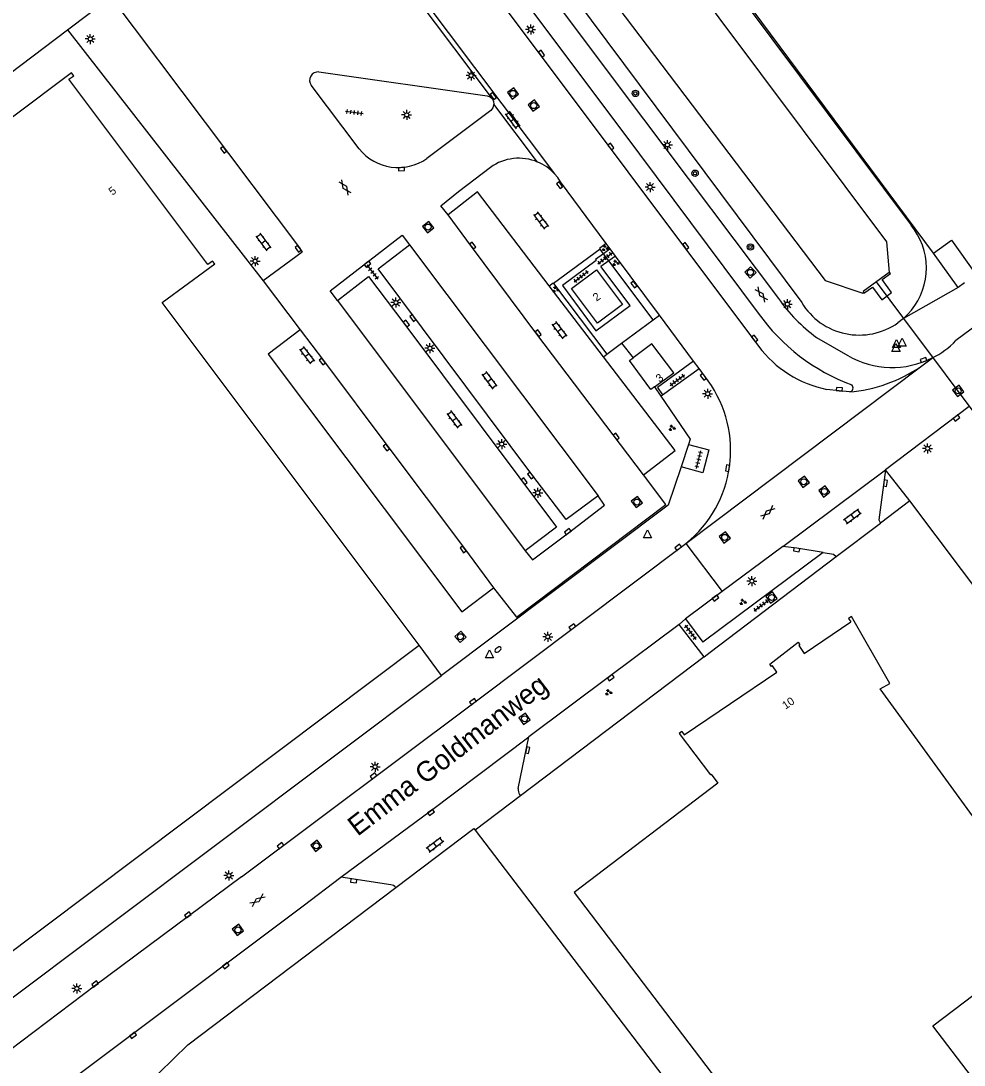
# Model space of a CAD drawing. Extents: x 126000 to 131009, y 393000 to 395500.
# Drawn here: x 130725.6 to 130843.4, y 394178.9 to 394309.3 of the extents above; entities that cross this region are included whole.
import ezdxf

# ---------------------------------------------------------------- set-up
doc = ezdxf.new("R2010")
doc.units = 0
for name, color, linetype in [('gg-afsc-hekwerk', 7, 'Continuous'), ('gg-anno-huisnummerreeks BGT', 7, 'Continuous'), ('gg-anno-openbare ruimte label', 7, 'Continuous'), ('gg-bbg-bijgebouw', 7, 'Continuous'), ('gg-bbg-hoofdgebouw', 7, 'Continuous'), ('gg-knt-verharding', 7, 'Continuous'), ('gg-knt-verharding nz', 7, 'Continuous'), ('gg-kntw-bovenkant insteek waterloop', 7, 'Continuous'), ('gg-kwrk-duiker nz buis', 7, 'Continuous'), ('gg-kwrk-uitstroombak niveau min 01', 7, 'Continuous'), ('gt-grn-groengrens', 7, 'Continuous'), ('gt-grn-weggrens', 7, 'Continuous'), ('gt-symb-boom', 7, 'Continuous'), ('gt-symb-brandkraan', 7, 'Continuous'), ('gt-symb-gesloten verharding', 7, 'Continuous'), ('gt-symb-groenvak', 7, 'Continuous'), ('gt-symb-klinker verharding', 7, 'Continuous'), ('gt-symb-kolk', 7, 'Continuous'), ('gt-symb-lichtmast', 7, 'Continuous'), ('gt-symb-rioolschacht', 7, 'Continuous'), ('gt-symb-tegel verharding', 7, 'Continuous'), ('gt-symb-waterafsluiter', 7, 'Continuous'), ('gx-grn-maaiveld', 7, 'Continuous')]:
    doc.layers.add(name, color=color, linetype=linetype)

# ---------------------------------------------------------------- blocks, each defined once
blk = doc.blocks.new('gt0-BOOM')
at = {"layer": 'gt-symb-boom'}
for radius in [0.4, 0.2]:
    blk.add_circle((0, 0), radius, dxfattribs=at)
blk = doc.blocks.new('gt0-LMAST')
at = {"layer": 'gt-symb-lichtmast'}
for p, q in [((-0.18, 0.17), (-0.45, 0.44)), ((0, 0.25), (0, 0.62)), ((0.17, 0.17), (0.44, 0.44)), ((-0.25, 0), (-0.63, 0)), ((-0.18, -0.18), (-0.45, -0.45)), ((0, -0.25), (0, -0.63)), ((0.44, -0.45), (0.17, -0.18)), ((0.25, 0), (0.62, 0))]:
    blk.add_line(p, q, dxfattribs=at)
blk.add_circle((0, 0), 0.25, dxfattribs=at)
blk = doc.blocks.new('gt0-GRVAK')
at = {"layer": 'gt-symb-groenvak'}
for p, q in [((-0.11, 0.19), (-0.23, 0.24)), ((-0.18, 0.15), (0.09, 0.15)), ((-0.09, 0.21), (-0.16, 0.32)), ((-0.05, 0.21), (-0.05, 0.39)), ((0, 0.21), (0.06, 0.32)), ((0.01, 0.19), (0.13, 0.24)), ((0.26, -0.05), (0.2, 0.06)), ((0.3, -0.05), (0.3, 0.13)), ((0.35, -0.05), (0.41, 0.06)), ((-0.25, -0.23), (-0.36, -0.18)), ((-0.32, -0.26), (-0.05, -0.26)), ((-0.23, -0.21), (-0.29, -0.1)), ((-0.18, -0.2), (-0.18, -0.02)), ((-0.14, -0.21), (-0.07, -0.1)), ((-0.12, -0.23), (0, -0.18)), ((0.24, -0.07), (0.12, -0.02)), ((0.17, -0.11), (0.44, -0.11)), ((0.37, -0.07), (0.49, -0.02))]:
    blk.add_line(p, q, dxfattribs=at)
blk = doc.blocks.new('gt0-KOLK')
at = {"layer": 'gt-symb-kolk'}
blk.add_lwpolyline([(0, 0), (0.38, 0), (0.38, 0.4), (-0.37, 0.4), (-0.37, 0), (0, 0)], dxfattribs=at)
blk = doc.blocks.new('gt0-TEG1')
at = {"layer": 'gt-symb-tegel verharding'}
for p, q in [((-1.12, 0), (1.12, 0)), ((-0.9, -0.25), (-0.9, 0.25)), ((-0.45, -0.25), (-0.45, 0.25)), ((0, -0.25), (0, 0.25)), ((0.45, -0.25), (0.45, 0.25)), ((0.9, -0.25), (0.9, 0.25))]:
    blk.add_line(p, q, dxfattribs=at)
blk = doc.blocks.new('gt0-RS')
at = {"layer": 'gt-symb-rioolschacht'}
blk.add_lwpolyline([(-0.5, -0.5), (0.5, -0.5), (0.5, 0.5), (-0.5, 0.5)], close=True, dxfattribs=at)
blk.add_circle((0, 0), 0.375, dxfattribs=at)
blk = doc.blocks.new('gt0-KL1')
at = {"layer": 'gt-symb-klinker verharding'}
for p, q in [((-1.15, 0.3), (1.15, 0.3)), ((-1, -0.3), (-1, 0.3)), ((-0.5, 0.3), (-0.5, 0.45)), ((0, -0.3), (0, 0.3)), ((0.5, 0.3), (0.5, 0.45)), ((1, -0.3), (1, 0.3)), ((-1.15, -0.3), (1.15, -0.3)), ((-0.5, -0.45), (-0.5, -0.3)), ((0.5, -0.45), (0.5, -0.3))]:
    blk.add_line(p, q, dxfattribs=at)
blk = doc.blocks.new('gt0-WAFSL')
at = {"layer": 'gt-symb-waterafsluiter'}
for p, q in [((-0.5, -0.33), (0, 0.67)), ((0, 0.67), (0.5, -0.33)), ((0.5, -0.33), (-0.5, -0.33))]:
    blk.add_line(p, q, dxfattribs=at)
blk = doc.blocks.new('gt0-GESVH1')
at = {"layer": 'gt-symb-gesloten verharding'}
for p, q in [((-0.99, -0.26), (0.01, 0.24)), ((0.01, -0.26), (-0.99, 0.24)), ((0.01, 0.24), (1.01, -0.26)), ((1.01, 0.24), (0.01, -0.26))]:
    blk.add_line(p, q, dxfattribs=at)
blk = doc.blocks.new('gt0-BR')
at = {"layer": 'gt-symb-brandkraan'}
for centre, radius, start, end in [((-0.24, 0), 0.206, 107.5669, 252.4331), ((0.6, -2.66), 3, 106.892, 107.5669), ((0, -0.69), 0.938, 73.108, 106.892), ((-0.6, -2.66), 3, 72.4331, 73.108), ((0.24, 0), 0.206, 287.567, 72.4331), ((0.6, 2.66), 3, 252.4331, 253.108), ((0, 0.69), 0.938, 253.108, 286.8921), ((-0.6, 2.66), 3, 286.8921, 287.567)]:
    blk.add_arc(centre, radius, start, end, dxfattribs=at)

msp = doc.modelspace()

# ---------------------------------------------------------------- linework, layer by layer
at = {"layer": 'gg-afsc-hekwerk'}
for p, q in [((130839.62, 394280.32), (130730.73, 394427.13)), ((130839.62, 394280.32), (130772.2, 394371.21)), ((130797.97, 394280.85), (130792.18, 394276.56)), ((130798.41, 394280.26), (130797.97, 394280.85)), ((130799.09, 394279.37), (130798.41, 394280.26)), ((130804.6, 394272.01), (130799.09, 394279.37)), ((130792.18, 394276.56), (130798.82, 394267.74)), ((130800.66, 394269.1), (130804.6, 394272.01)), ((130798.82, 394267.74), (130800.66, 394269.1)), ((130800.66, 394269.1), (130802.09, 394267.28)), ((130804.78, 394263.66), (130805.58, 394262.49)), ((130809.03, 394256.44), (130808.1, 394253.66)), ((130836.65, 394249.39), (130833.02, 394246.64)), ((130896.14, 394170.36), (130836.65, 394249.39)), ((130827.47, 394242.44), (130833.02, 394246.64)), ((130811.71, 394230.51), (130827.47, 394242.44)), ((130778.17, 394227.61), (130775.4, 394231.4)), ((130810.96, 394229.93), (130811.71, 394230.51)), ((130810.96, 394229.93), (130788.05, 394212.57)), ((130674.43, 394149.73), (130778.17, 394227.61)), ((130788.05, 394212.57), (130782.38, 394208.28)), ((130782.38, 394208.28), (130824.29, 394153.36))]:
    msp.add_line(p, q, dxfattribs=at)
for points in [[(130805.58, 394262.49), (130809.25, 394257.09), (130809.03, 394256.44)], [(130808.1, 394253.66), (130806.48, 394248.85), (130778.17, 394227.61)], [(130772.45, 394201.12), (130782.21, 394208.5), (130782.38, 394208.28)], [(130725.71, 394163.65), (130727.62, 394165.25), (130737.58, 394172.73), (130739.41, 394174.39), (130742.89, 394177.98), (130746.47, 394181.48), (130772.45, 394201.12)]]:
    msp.add_lwpolyline(points, dxfattribs=at)
at = {"layer": 'gg-bbg-bijgebouw'}
for p, q in [((130842.69, 394276.05), (130839.62, 394280.32)), ((130843.49, 394276.63), (130842.69, 394276.05))]:
    msp.add_line(p, q, dxfattribs=at)
msp.add_lwpolyline([(130839.62, 394280.32), (130841.86, 394281.96), (130844.89, 394277.75)], dxfattribs=at)
at = {"layer": 'gg-bbg-hoofdgebouw'}
msp.add_line((130671.64, 394153.43), (130775.4, 394231.4), dxfattribs=at)
for points in [[(130775.4, 394231.4), (130743.26, 394274.17), (130749.85, 394278.99), (130749.57, 394279.36), (130748.97, 394278.92), (130731.63, 394302.05), (130732.23, 394302.5), (130731.96, 394302.86), (130724.59, 394297.33), (130721.82, 394300.97)], [(130794.42, 394275.93), (130797.55, 394278.27), (130800.77, 394273.94), (130797.67, 394271.61), (130794.42, 394275.93)], [(130804.78, 394263.66), (130807.17, 394265.39), (130804.44, 394269.03), (130802.09, 394267.28)], [(130804.78, 394263.66), (130804.32, 394263.33), (130801.64, 394266.95), (130802.09, 394267.28)], [(130808.18, 394220.62), (130808.5, 394220.18), (130820.05, 394228.02), (130819.51, 394228.81), (130819.38, 394228.73), (130819.17, 394229.03), (130822.72, 394231.76), (130822.94, 394231.43), (130822.82, 394231.35), (130823.49, 394230.35), (130829.28, 394234.29)], [(130848.64, 394171.9), (130839.55, 394183.84), (130855.04, 394195.59), (130832.97, 394225.91), (130834.19, 394226.6), (130829.38, 394234.95), (130829.02, 394234.73), (130829.28, 394234.29)], [(130808.18, 394220.62), (130807.84, 394220.37), (130811.77, 394215.21), (130811.85, 394215.26), (130812.68, 394214.15), (130794.75, 394200.51), (130828.31, 394156.42)]]:
    msp.add_lwpolyline(points, dxfattribs=at)
at = {"layer": 'gg-knt-verharding'}
for p, q in [((130732.16, 394370.3), (130792.27, 394290.26)), ((130755.2, 394352.22), (130817.77, 394268.72)), ((130784.52, 394299.61), (130748.05, 394348.26)), ((130721.82, 394300.97), (130731.44, 394308.25)), ((130731.44, 394308.25), (130755.89, 394276.89)), ((130767.89, 394293.35), (130761.89, 394301.31)), ((130790.18, 394291.72), (130784.72, 394298.93)), ((130774.17, 394281.4), (130797.73, 394250.02)), ((130799.25, 394280.87), (130798.74, 394281.56)), ((130799.25, 394280.87), (130798.41, 394280.26)), ((130799.92, 394279.96), (130799.09, 394279.37)), ((130799.92, 394279.96), (130799.25, 394280.87)), ((130805.4, 394272.58), (130799.92, 394279.96)), ((130799.09, 394279.37), (130798.09, 394278.66)), ((130755.89, 394276.89), (130760.5, 394270.77)), ((130798.4, 394267.41), (130791.63, 394276.26)), ((130765.16, 394274.41), (130788.6, 394243.16)), ((130849.69, 394274.83), (130842.42, 394269.42)), ((130809.66, 394266.84), (130805.4, 394272.58)), ((130825.02, 394269.82), (130828.91, 394267.56)), ((130810.34, 394265.93), (130809.66, 394266.84)), ((130837.99, 394266.14), (130839.48, 394267.26)), ((130805.78, 394262.63), (130810.34, 394265.93)), ((130811.47, 394264.4), (130810.34, 394265.93)), ((130844.08, 394261.18), (130833.64, 394253.28)), ((130820.8, 394243.71), (130833.64, 394253.28)), ((130820.8, 394243.71), (130813.23, 394238.07)), ((130825.85, 394242.95), (130810.81, 394231.74)), ((130813.23, 394238.07), (130808.66, 394234.66)), ((130807.86, 394233.96), (130808.66, 394234.66)), ((130808.66, 394234.66), (130810.81, 394231.74)), ((130810.96, 394229.93), (130807.86, 394233.96)), ((130787.73, 394213.47), (130789.08, 394219.92)), ((130787.93, 394212.74), (130788.05, 394212.57)), ((130771.83, 394201.46), (130765.58, 394202.39))]:
    msp.add_line(p, q, dxfattribs=at)
for points in [[(130756.54, 394359.62), (130803.42, 394297.08), (130820.25, 394274.68)], [(130755.59, 394355.83), (130802.91, 394292.71), (130817.73, 394272.84)], [(130731.44, 394308.25), (130736.87, 394312.34), (130760.42, 394280.99), (130760.77, 394280.46), (130755.89, 394276.89)], [(130762.85, 394302.97), (130783.86, 394299.97), (130784.23, 394299.85), (130784.52, 394299.61)], [(130784.52, 394299.61), (130784.68, 394299.28), (130784.72, 394298.93)], [(130784.72, 394298.93), (130784.6, 394298.49), (130784.32, 394298.14), (130776.34, 394292.17)], [(130779, 394285.13), (130778.09, 394286.26), (130780.28, 394288.05), (130784.29, 394291.06)], [(130798.74, 394281.56), (130793.04, 394289.24), (130792.68, 394289.77), (130792.27, 394290.26)], [(130791.63, 394276.26), (130782.67, 394287.99), (130779, 394285.13)], [(130803.39, 394252.64), (130790.09, 394270.24), (130781.9, 394281.17), (130779, 394285.13)], [(130765.16, 394274.41), (130764.26, 394275.63), (130773.27, 394282.58), (130774.17, 394281.4)], [(130797.73, 394250.02), (130793.73, 394247.06), (130789.46, 394252.68), (130770.25, 394278.39), (130774.17, 394281.4)], [(130798.74, 394281.56), (130797.91, 394280.94), (130797.97, 394280.85)], [(130798.41, 394280.26), (130797.42, 394279.54), (130797.5, 394279.43)], [(130797.5, 394279.43), (130793.28, 394276.3), (130797.45, 394270.66), (130801.73, 394273.8), (130798.09, 394278.66)], [(130765.16, 394274.41), (130769.05, 394277.44), (130773.61, 394271.43), (130792.54, 394246.11), (130788.6, 394243.16)], [(130791.63, 394276.26), (130792.13, 394276.63), (130792.18, 394276.56)], [(130760.5, 394270.77), (130756.52, 394267.72), (130780.72, 394235.54), (130784.68, 394238.53)], [(130760.5, 394270.77), (130763.45, 394266.92), (130771.45, 394256.19), (130781.03, 394243.46), (130784.68, 394238.53)], [(130803.39, 394252.64), (130807.37, 394255.68), (130798.4, 394267.41)], [(130809.66, 394266.84), (130805.14, 394263.58), (130805.78, 394262.63)], [(130829.13, 394263.01), (130827.84, 394263.14), (130826.31, 394263.33)], [(130809.03, 394256.44), (130811.57, 394255.78), (130810.82, 394252.91), (130808.1, 394253.66)], [(130784.68, 394238.53), (130787.53, 394234.89), (130806.21, 394248.95), (130803.39, 394252.64)], [(130833.64, 394253.28), (130832.81, 394247.02), (130833.02, 394246.64)], [(130788.6, 394243.16), (130789.52, 394242.04), (130794.05, 394245.4), (130798.55, 394248.85), (130797.73, 394250.02)], [(130753.19, 394202.47), (130782.21, 394224.17), (130808.7, 394244.09)], [(130825.85, 394242.95), (130822.56, 394243.48), (130820.8, 394243.71)], [(130825.85, 394242.95), (130827.12, 394242.75), (130827.47, 394242.44)], [(130807.86, 394233.96), (130799.15, 394227.49), (130789.08, 394219.92)], [(130765.58, 394202.39), (130776.74, 394210.65), (130789.08, 394219.92)], [(130753.19, 394202.47), (130735.01, 394188.91), (130722.61, 394179.58), (130709.4, 394169.72)], [(130717.63, 394166.42), (130760.9, 394198.81), (130765.58, 394202.39)]]:
    msp.add_lwpolyline(points, dxfattribs=at)
for centre, radius, start, end in [((130762.75, 394301.91), 1.06, 84.736, 215.1078), ((130772.74, 394297.25), 6.22, 218.7563, 305.3463), ((130787.82, 394286.11), 6.08, 67.1895, 125.5677), ((130787.82, 394286.11), 6.09, 42.9576, 67.1724), ((130837.23, 394286.56), 20.72, 214.9856, 233.8954), ((130838.13, 394287.38), 25.05, 215.4913, 249.6587), ((130834.48, 394277.16), 11.1, 296.7731, 315.7379), ((130829.11, 394277.21), 14.17, 216.8461, 258.5885), ((130834.47, 394277.17), 11.1, 239.913, 296.7804), ((130799.4, 394255.7), 14.88, 308.7019, 35.7911), ((130829.07, 394263.52), 0.511, 276.9004, 46.582), ((130788.87, 394213.38), 1.14, 175.466, 214.358), ((130771.76, 394200.61), 0.857, 36.7807, 85.3627)]:
    msp.add_arc(centre, radius, start, end, dxfattribs=at)
at = {"layer": 'gg-knt-verharding nz'}
msp.add_arc((130827.59, 394281.49), 18.54, 274.7654, 304.0998, dxfattribs=at)
at = {"layer": 'gg-kntw-bovenkant insteek waterloop'}
msp.add_line((130835.86, 394272.18), (130835.18, 394271.65), dxfattribs=at)
msp.add_lwpolyline([(130835.86, 394272.18), (130836.41, 394272.71), (130836.86, 394273.22), (130837.28, 394273.79), (130837.66, 394274.4), (130837.98, 394275.04), (130838.25, 394275.71), (130838.46, 394276.39), (130838.61, 394277.09), (130838.7, 394277.8), (130838.73, 394278.52), (130838.7, 394279.24), (130838.61, 394279.95), (130838.45, 394280.65), (130838.24, 394281.33), (130837.97, 394281.99), (130837.64, 394282.63), (130837.26, 394283.24), (130836.83, 394283.82)], dxfattribs=at)
msp.add_arc((130830.34, 394278.5), 8.39, 211.1238, 305.2186, dxfattribs=at)
at = {"layer": 'gg-kwrk-duiker nz buis'}
for p, q in [((130832.45, 394276.74), (130835.86, 394272.18)), ((130835.86, 394272.18), (130848.03, 394255.9))]:
    msp.add_line(p, q, dxfattribs=at)
at = {"layer": 'gg-kwrk-uitstroombak niveau min 01'}
for points in [[(130834.08, 394277.94), (130830.82, 394275.54), (130830.9, 394275.42)], [(130834.39, 394275.43), (130833.21, 394277.04), (130834.24, 394277.79), (130834.12, 394277.97), (130834.08, 394277.94)], [(130830.9, 394275.42), (130830.94, 394275.36), (130831.99, 394276.1), (130833.17, 394274.5), (130834.39, 394275.43)]]:
    msp.add_lwpolyline(points, dxfattribs=at)
at = {"layer": 'gt-grn-groengrens'}
for p, q in [((130842.69, 394276.05), (130835.86, 394272.18)), ((130804.6, 394272.01), (130805.4, 394272.58)), ((130798.4, 394267.41), (130798.82, 394267.74)), ((130805.58, 394262.49), (130805.78, 394262.63)), ((130836.65, 394249.39), (130833.64, 394253.28))]:
    msp.add_line(p, q, dxfattribs=at)
at = {"layer": 'gt-grn-weggrens'}
for q in [(130837.99, 394266.14), (130813.23, 394238.07)]:
    msp.add_line((130808.7, 394244.09), q, dxfattribs=at)
at = {"layer": 'gx-grn-maaiveld'}
for points in [[(130771.77, 394370.89), (130774.14, 394367.71), (130836.83, 394283.82)], [(130768.78, 394368.6), (130770.91, 394365.74), (130833.75, 394281.76), (130834.08, 394277.94)], [(130761, 394362.8), (130765.91, 394356.29), (130826.08, 394276.93), (130830.8, 394275.35), (130830.9, 394275.42)], [(130758.32, 394360.97), (130764.43, 394352.96), (130823.16, 394274.17)]]:
    msp.add_lwpolyline(points, dxfattribs=at)

# ---------------------------------------------------------------- block references
at = {"layer": 'gt-symb-boom'}
for p in [(130802.39, 394300.29), (130809.84, 394290.32), (130816.76, 394281.11)]:
    msp.add_blockref('gt0-BOOM', p, dxfattribs=at)
at = {"layer": 'gt-symb-brandkraan', "rotation": 36.86989764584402}
msp.add_blockref('gt0-BR', (130785.22, 394230.83), dxfattribs=at)
at = {"layer": 'gt-symb-gesloten verharding'}
for p, rotation in [((130766.1, 394288.56), -55.594765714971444), ((130818.12, 394275.18), -53.130102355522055), ((130818.93, 394247.96), -138.24275297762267), ((130755.18, 394199.55), 36.789699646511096)]:
    msp.add_blockref('gt0-GESVH1', p, dxfattribs=dict(at, rotation=rotation))
at = {"layer": 'gt-symb-groenvak'}
for p in [(130798.61, 394280.96), (130799.93, 394279.1), (130792.41, 394275.8), (130806.95, 394258.5), (130815.81, 394236.77), (130799.03, 394225.48)]:
    msp.add_blockref('gt0-GRVAK', p, dxfattribs=at)
at = {"layer": 'gt-symb-klinker verharding'}
for p, rotation in [((130787.09, 394296.97), 125.88411316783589), ((130790.59, 394284.42), -52.63746931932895), ((130755.91, 394281.74), -53.130102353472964), ((130792.88, 394270.72), -53.130102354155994), ((130761.36, 394267.6), -53.17596648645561), ((130784.14, 394264.47), -53.130102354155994), ((130779.76, 394259.57), -53.13010235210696), ((130829.5, 394247.43), -143.62293247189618), ((130777.36, 394206.43), -142.84362584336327)]:
    msp.add_blockref('gt0-KL1', p, dxfattribs=dict(at, rotation=rotation))
at = {"layer": 'gt-symb-kolk'}
for p, rotation in [((130790.5, 394305.14), -53.256203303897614), ((130784.8, 394300.08), 126.78969964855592), ((130799.16, 394293.55), -53.256203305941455), ((130751.11, 394293.36), 126.86989764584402), ((130773.17, 394291.04), -175.98782884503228), ((130793.08, 394288.94), 126.9157067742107), ((130760.42, 394280.99), 126.95012773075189), ((130781.9, 394281.17), -53.130102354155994), ((130808.52, 394281.12), -53.256203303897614), ((130768.81, 394279.12), -142.27073011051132), ((130802.38, 394276.54), 126.78969964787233), ((130773.61, 394271.43), -52.843625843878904), ((130774.76, 394272.36), 126.74379669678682), ((130790.09, 394270.24), -53.004102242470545), ((130817.13, 394269.57), -53.256203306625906), ((130763.45, 394266.92), 127.44283634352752), ((130838.44, 394266.8), 20.918204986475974), ((130811.02, 394265), 126.70953402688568), ((130827.84, 394263.14), -4.934985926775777), ((130842.38, 394259.91), -143.4165788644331), ((130799.83, 394257.32), -52.763341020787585), ((130771.45, 394256.19), 126.70953402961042), ((130814.11, 394253.45), 81.19719553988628), ((130788.34, 394251.75), -53.175966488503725), ((130789.46, 394252.68), 127.23665897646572), ((130833.42, 394251.65), -97.81418085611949), ((130794.05, 394245.4), 36.50328298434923), ((130781.03, 394243.46), 126.95012773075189), ((130807.85, 394243.44), 36.95012773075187), ((130822.56, 394243.48), 170.90519501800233), ((130812.27, 394237.42), -142.96961039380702), ((130794.63, 394233.51), 36.95012773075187), ((130799.19, 394227.48), -142.96961039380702), ((130782.21, 394224.17), 36.9501277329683), ((130788.74, 394218.31), -101.82589709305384), ((130769.8, 394214.89), 37.03038960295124), ((130776.74, 394210.65), -143.49671701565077), ((130758.17, 394206.18), 37.03038960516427), ((130767.24, 394202.14), 171.56061323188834), ((130746.6, 394197.54), 36.7896996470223), ((130751.11, 394191.51), -143.13010235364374), ((130735.01, 394188.91), 36.66359246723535), ((130739.53, 394182.81), -143.130102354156)]:
    msp.add_blockref('gt0-KOLK', p, dxfattribs=dict(at, rotation=rotation))
at = {"layer": 'gt-symb-lichtmast'}
for p in [(130789.31, 394308.28), (130734.3, 394307.09), (130781.87, 394302.52), (130773.82, 394297.61), (130806.39, 394293.85), (130804.22, 394288.6), (130754.89, 394279.34), (130772.47, 394274.17), (130821.37, 394273.97), (130776.72, 394268.46), (130811.42, 394262.79), (130785.69, 394256.5), (130838.88, 394255.95), (130790.19, 394250.42), (130816.94, 394239.38), (130791.45, 394232.43), (130769.88, 394216.2), (130751.61, 394202.61), (130732.62, 394188.51)]:
    msp.add_blockref('gt0-LMAST', p, dxfattribs=at)
at = {"layer": 'gt-symb-rioolschacht'}
for p, rotation in [((130787.1, 394300.29), -53.08429322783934), ((130789.69, 394298.77), -53.08429322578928), ((130776.49, 394283.6), 128.25701687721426), ((130816.75, 394277.94), 42.40480040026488), ((130842.71, 394263.14), -53.08429322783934), ((130823.42, 394251.79), -53.084293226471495), ((130825.99, 394250.58), -53.08429322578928), ((130802.57, 394249.26), 36.99589775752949), ((130813.55, 394244.84), 36.789699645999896), ((130819.39, 394237.34), 35.85054811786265), ((130780.54, 394232.44), 41.30991847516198), ((130788.54, 394222.19), 35.96415629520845), ((130762.53, 394206.32), 36.789699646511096), ((130752.74, 394195.82), 36.7896996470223)]:
    msp.add_blockref('gt0-RS', p, dxfattribs=dict(at, rotation=rotation))
at = {"layer": 'gt-symb-tegel verharding'}
for p, rotation in [((130767.29, 394297.91), -7.465974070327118), ((130798.6, 394279.7), 37.52317188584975), ((130769.54, 394277.99), -51.698006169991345), ((130795.62, 394277.43), 37.52317188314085), ((130807.63, 394264.48), 35.88411316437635), ((130810.3, 394254.55), 75.82485794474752), ((130818.1, 394236.33), 36.824033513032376), ((130809.26, 394233), -53.46261365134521)]:
    msp.add_blockref('gt0-TEG1', p, dxfattribs=dict(at, rotation=rotation))
at = {"layer": 'gt-symb-waterafsluiter'}
for p in [(130835.01, 394268.9), (130835.73, 394269.04), (130834.94, 394268.39), (130803.92, 394245.12), (130784.15, 394230.12)]:
    msp.add_blockref('gt0-WAFSL', p, dxfattribs=at)

# ---------------------------------------------------------------- texts
at = {"layer": 'gg-anno-huisnummerreeks BGT'}
for s, rotation, p in [('5', 36.9, (130737.06, 394287.5)), ('2', 36.7, (130797.54, 394274.27)), ('3', 36.5, (130805.4, 394264.14)), ('10', 34.2, (130821.14, 394223.32))]:
    msp.add_text(s, height=1, rotation=rotation, dxfattribs=at).set_placement(p)
at = {"layer": 'gg-anno-openbare ruimte label'}
msp.add_text('Emma Goldmanweg', height=2.5, rotation=37.6, dxfattribs=at).set_placement((130767.69, 394207.44))

doc.saveas('drawing.dxf')
